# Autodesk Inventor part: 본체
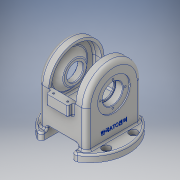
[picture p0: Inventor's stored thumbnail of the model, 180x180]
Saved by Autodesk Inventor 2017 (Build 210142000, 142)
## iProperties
Part Number: 본체
Material: 알루미늄 6061
Document SubType Name: Modeling
Designer: MRC
Density: 2.7 g/cm^3
Appearance: 알루미늄 - 평지
Mass: 1246.18 g
Surface Area: 1059.64 cm^2
Volume: 461.547 cm^3
Author: MRC
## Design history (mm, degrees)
sketch "스케치1"
  geometry: L1 (0, 0)-(0, -71); L2 (28, -65.246)-(28, 0); L3 (-28, -65.246)-(-28, 0); L4 (28, 0)-(28, 65.246); L5 (-28, 0)-(-28, 65.246); A1 r 71 centre (0, 0) between (0, -71) and (28, -65.246); 1 further point
  constraints: 10 end point, 5 point on circle, 3 vertical, 1 centre point, 1 coincident
  dimensions: "d0" = 142 diameter of A1; "d1" = 28 distance between parallel lines of L1 L2; "d2" = 28 distance between parallel lines of L1 L3
extrude "돌출1" new body sketch "스케치1" distance "d3" = 13; taper "d4" = 0 deg
fillet "모깎기1" dims "d5" = 6
sketch "스케치2"
  geometry: L1 (0, 0)-(81, 0); L2 (13, -60.512)-(0, -60.512) reference; L3 (13, 60.512)-(13, -60.512) reference; L4 (0, 60.512)-(13, 60.512) reference; L5 (0, 60.512)-(0, -60.512) reference; L6 (81, 0)-(81, 51); L7 (81, 51)-(13, 51); L8 (81, 0)-(81, -51); L9 (81, -51)-(13, -51); L10 (0, 51)-(0, -51); L11 (13, -60.512)-(13, 60.512) reference; L12 (13, 51)-(13, -51); A1 r 51 centre (81, 0) between (81, -51) and (81, 51)
  constraints: 14 end point, 5 point on line, 3 perpendicular, 2 point on circle, 1 centre point, 1 coincident, 1 horizontal, 1 vertical
  dimensions: "d6" = 81 distance of L1.start L1.end; "d7" = 102 diameter of A1
extrude "돌출2" join sketch "스케치2" stored distance "d8" = 88; taper "d9" = 0 deg
sketch "스케치3"
  geometry: L1 (-44, 81)-(44, 81) reference; L2 (44, 81)-(44, 81) reference; L3 (-44, 81)-(44, 81) reference; L4 (-44, 81)-(-44, 81) reference; L5 (-44, 81)-(44, 81) reference; L6 (44, 13)-(44, 81) reference; L7 (28, 13)-(44, 13) reference; L8 (-28, 13)-(28, 13) reference; L9 (-44, 13)-(-28, 13) reference; L10 (-44, 81)-(-44, 13) reference; L11 (-44, 81)-(44, 81) reference; L12 (0, 81)-(-25, 81); L13 (-25, 81)-(25, 81); L14 (25, 81)-(25, 141); L15 (25, 141)-(-25, 141); L16 (-25, 141)-(-25, 81); 1 further point
  constraints: 10 end point, 2 parallel, 1 coincident, 1 horizontal, 1 midpoint, 1 perpendicular, 1 point on line
  dimensions: "d15" = 25 distance of L12.start L12.end; "d16" = 50 distance of L15.end L14.end; "d17" = 60 distance of L14.end L13.end
extrude "돌출3" cut sketch "스케치3" stored distance "d18" = 146.5; taper "d19" = 0 deg
node "작업 평면1"
sketch "스케치5"
  geometry: L1 (39, 46)-(-39, 46); L2 (-39, 46)-(-39, -46); L3 (-39, -46)-(39, -46); L4 (39, -46)-(39, 46); L5 (39, 46)-(-39, -46); L6 (-39, 46)-(39, -46); 1 further point
  constraints: 12 end point, 2 midpoint, 2 parallel, 1 horizontal, 1 perpendicular
  dimensions: "d23" = 78 distance of L3.end L2.end; "d24" = 92 distance of L2.end L1.end
extrude "돌출4" cut sketch "스케치5" distance "d25" = 41; taper "d26" = 0 deg
sketch "스케치6"
  geometry: L1 (51, 0)-(51, -68) reference; L2 (-51, -68)-(51, -68) reference; L3 (-51, -68)-(-51, 0) reference; L4 (-51, 0)-(51, 0); L5 (46, -41)-(46, 0) reference; L6 (-46, 0)-(46, 0); L7 (46, 0)-(-46, 0) reference; L8 (0, 0)-(0, 46); A1 r 51 centre (0, 0) between (51, 0) and (-51, 0) reference; A2 r 46 centre (0, 0) between (46, 0) and (-46, 0); 1 further point
  constraints: 6 end point, 3 point on circle, 3 point on line, 1 centre point, 1 coincident, 1 collinear, 1 perpendicular, 1 vertical
  dimensions: "d28" = 46 distance of L8.start L8.end
extrude "돌출5" cut sketch "스케치6" distance "d29" = 14; taper "d30" = 0 deg
sketch "스케치7"
  geometry: C1 r 33.5 at (46, 41); A1 r 51 centre (46, 41) between (97, 41) and (-5, 41) reference; 1 further point
  constraints: 1 centre point, 1 coincident
  dimensions: "d31" = 67 diameter of C1
extrude "돌출6" join sketch "스케치7" distance "d32" = 12; taper "d33" = -45 deg
sketch "스케치8"
  geometry: C1 r 30 at (0, 81); A1 r 51 centre (0, 81) between (51, 81) and (-51, 81) reference; 1 further point
  constraints: 1 centre point, 1 coincident
  dimensions: "d34" = 60 diameter of C1
extrude "돌출7" cut sketch "스케치8" distance "d35" = 2; taper "d36" = 0 deg
sketch "스케치9"
  geometry: C1 r 30 at (0, 0) reference; C2 r 18.5 at (0, 0); 1 further point
  constraints: 1 centre point, 1 coincident
  dimensions: "d37" = 37 diameter of C2
extrude "돌출8" cut sketch "스케치9" distance "d38" = 13; taper "d39" = 0 deg
sketch "스케치10"
  geometry: C1 r 18.5 at (0, 0) reference; C2 r 16 at (0, 0); 1 further point
  constraints: 1 centre point, 1 coincident
  dimensions: "d40" = 32 diameter of C2
extrude "돌출9" cut sketch "스케치10" distance "d41" = 13; taper "d42" = 0 deg
sketch "스케치11"
  geometry: C1 r 30 at (28, 51); 1 further point
  constraints: 1 centre point, 1 coincident
  dimensions: "d43" = 60 diameter of C1
extrude "돌출10" cut sketch "스케치11" distance "d44" = 70.75; taper "d45" = 0 deg
sketch "스케치12"
  geometry: C1 r 30 at (28, 51); 1 further point
  constraints: 1 centre point, 1 coincident
  dimensions: "d46" = 60 diameter of C1
extrude "돌출11" cut sketch "스케치12" distance "d47" = 9; taper "d48" = 0 deg
sketch "스케치13"
  geometry: C1 r 14 at (0, 0); 1 further point
  constraints: 1 centre point, 1 coincident
  dimensions: "d49" = 28 diameter of C1
extrude "돌출12" cut sketch "스케치13" distance "d50" = 15; taper "d51" = 0 deg
sketch "스케치14"
  geometry: C1 r 11 at (0, 0); 1 further point
  constraints: 1 centre point, 1 coincident
  dimensions: "d52" = 22 diameter of C1
extrude "돌출13" cut sketch "스케치14" distance "d53" = 15; taper "d54" = 0 deg
sketch "스케치15" dims "d55" = 46
  geometry: L1 (0, 0)-(0, 23); C1 r 30 at (0, 0) reference; 2 further points
  constraints: 2 end point, 1 coincident, 1 vertical, 1 vertical alignment, 2 other
hole "구멍1" sketch "스케치15" at (0, 23) diameter "d56" = 3.242; stored, may be unused: countersink angle "d60" = 90 deg, drill point angle "d62" = 118 deg; dims "d57" = 8, "d58" = 4, "d59" = 2, "d61" = 10
node "작업 평면2"
sketch "스케치16"
  geometry: L1 (0, 0)-(0, -61); L2 (0, -61)-(20, -61); L3 (20, -61)-(20, -46); L4 (-39, -46)-(39, -46) reference; L5 (20, -46)-(-20, -46); L6 (-20, -46)-(-20, -61); L7 (-20, -61)-(0, -61)
  constraints: 12 end point, 3 perpendicular, 2 point on line, 1 horizontal, 1 vertical
  dimensions: "d67" = 61 distance of L1.start L1.end; "d68" = 20 distance of L1.end L2.end; "d69" = 40 distance of L3.end L5.end
extrude "돌출14" join sketch "스케치16" distance "d70" = 20; taper "d71" = 0 deg
sketch "스케치17"
  geometry: L1 (45, 0)-(50, 0) reference; L2 (50, 5)-(50, 0) reference; L3 (50, 5)-(0, 5) reference; L4 (0, 0)-(0, 5) reference; L5 (0, 0)-(5, 0) reference; L6 (5, -10)-(5, 0) reference; L7 (45, -10)-(5, -10) reference; L8 (45, 0)-(45, -10) reference; L9 (38, 105)-(12, 105); L10 (12, 105)-(12, -3); L11 (12, -3)-(38, -3); L12 (38, -3)-(38, 105); L13 (38, 105)-(12, -3); L14 (12, 105)-(38, -3); 5 further points
  constraints: 12 end point, 4 coincident, 2 midpoint, 2 parallel, 1 horizontal, 1 perpendicular
  dimensions: "d72" = 26 distance of L11.end L10.end; "d73" = 108 distance of L10.end L9.end
hole "구멍2" sketch "스케치17" at (12, -3), (38, -3), (12, 105), (38, 105) diameter "d74" = 3.242; stored, may be unused: countersink angle "d78" = 90 deg, drill point angle "d80" = 118 deg; dims "d75" = 8, "d76" = 4, "d77" = 2, "d79" = 10
sketch "스케치18"
  geometry: L1 (-55, 25)-(55, 25); L2 (55, 25)-(55, -25); L3 (55, -25)-(-55, -25); L4 (-55, -25)-(-55, 25); L5 (-55, 25)-(55, -25); L6 (55, 25)-(-55, -25); 5 further points
  constraints: 12 end point, 4 coincident, 2 midpoint, 2 parallel, 1 horizontal, 1 perpendicular
  dimensions: "d81" = 110 distance of L2.end L3.end; "d82" = 50 distance of L1.end L2.end
hole "구멍3" sketch "스케치18" at (55, -25), (55, 25), (-55, -25), (-55, 25) diameter "d83" = 9; stored, may be unused: countersink angle "d87" = 90 deg, drill point angle "d89" = 118 deg; dims "d84" = 8, "d85" = 15, "d86" = 8.8, "d88" = 10
fillet "모깎기2" dims "d90" = 0.3
chamfer "모따기1" distance "d91" = 1; stored, may be unused: second distance "d92" = 2, angle "d93" = 45 deg
fillet "모깎기3" dims "d94" = 3
fillet "모깎기4" dims "d95" = 3
fillet "모깎기5" dims "d96" = 8
fillet "모깎기9" dims "d100" = 3
sketch "스케치19" dims "d101" = 46
  geometry: L1 (0, 0)-(0, 23); 1 further point
  constraints: 2 end point, 1 coincident, 1 vertical, 1 vertical alignment, 2 other
hole "구멍4" sketch "스케치19" at (0, 23) diameter "d102" = 3.242; stored, may be unused: countersink angle "d106" = 90 deg, drill point angle "d108" = 118 deg; dims "d103" = 8, "d104" = 15, "d105" = 8.8, "d107" = 10
chamfer "모따기2" distance "d112" = 1; stored, may be unused: second distance "d113" = 2, angle "d114" = 45 deg
fillet "모깎기10" dims "d115" = 3
fillet "모깎기11" dims "d116" = 3
fillet "모깎기12" dims "d117" = 3
sketch "스케치20"
  geometry: L1 (60.512, 0)-(-60.512, 0) reference; 3 further points
  constraints: 1 midpoint, 1 vertical alignment, 1 other
  dimensions: "d118" = 30 distance from line of L1 point (0, 30)
feature "엠보싱1" sketch "스케치20" dims "d119" = 0.5, "d120" = 0
sketch "스케치22"
  geometry: L1 (0, 0)-(0, 19); L2 (-28, 0)-(-37.138, 0) reference; L3 (0, 0)-(-28, 0); L4 (-28, 0)-(-28, 19); L5 (-31, 16)-(31, 16) reference; L6 (-28, 19)-(0, 19)
  constraints: 8 end point, 1 horizontal, 1 parallel, 1 perpendicular, 1 vertical
  dimensions: "d123" = 19 distance of L1.start L1.end
revolve "회전1" sketch "스케치22" stored, may be unused: angle "d124" = 90 deg
sketch "스케치23"
  geometry: L1 (64, -71)-(73.138, -71) reference; L2 (64, -71)-(64, -81) reference; L3 (64, -81)-(73.138, -81) reference; L4 (73.138, -81)-(73.138, -71) reference; L5 (71.569, -68)-(67, -68) reference; L6 (64, -71)-(73.138, -71) reference; L7 (67, -68)-(67, -65) reference; L8 (36, -81)-(64, -81); L9 (64, -81)-(64, -62); L10 (64, -62)-(36, -62); L11 (36, -62)-(36, -81); L12 (8, -62)-(36, -62); L13 (36, -81)-(8, -81); L14 (8, -81)-(8, -62); A1 r 3 centre (67, -71) between (67, -68) and (64, -71) reference; 1 further point; 1 other entity
  constraints: 14 end point, 2 parallel, 2 symmetric about line, 1 horizontal, 1 perpendicular, 1 other
  dimensions: "d125" = 28 distance of L10.end L9.end; "d126" = 19 distance of L9.end L8.end
extrude "돌출16" cut sketch "스케치23" distance "d127" = 138.75; taper "d128" = 0 deg
fillet "모깎기13" dims "d129" = 3
fillet "모깎기14" dims "d130" = 3
fillet "모깎기15" dims "d131" = 3
node "솔리드1"
mirror "미러1"
mirror "미러2"
pattern_circular "원형 패턴1" dims angle "d64" = 360 deg
mirror "미러3"
mirror "미러4"
pattern_circular "원형 패턴2" dims angle "d110" = 360 deg
node "투영된 루프1"
node "투영된 루프2"
node "투영된 루프3"
node "투영된 루프4"
node "투영된 루프5"
node "투영된 루프7"
node "투영된 루프8"
other parameters: "d66" = 81
